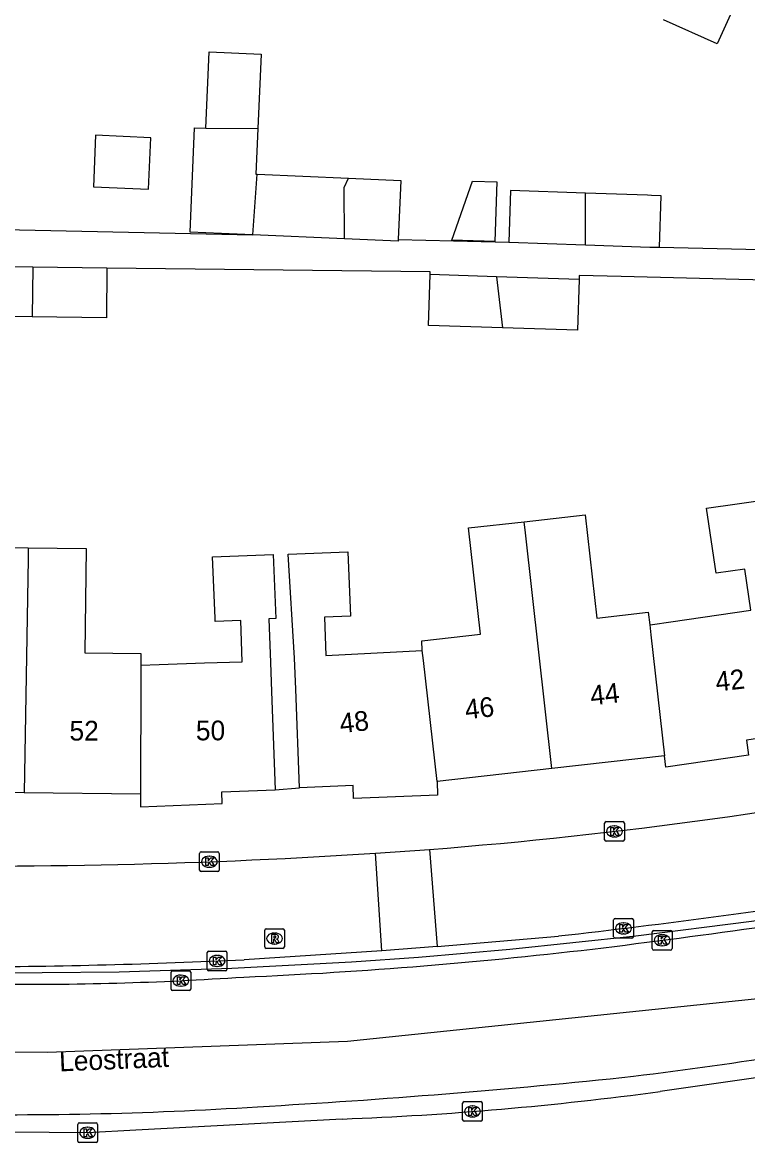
# Model space of a CAD drawing. Extents: x 161845 to 162341, y 381620 to 382158.
# Drawn here: x 162150.7 to 162187.5, y 381620.1 to 381677 of the extents above; entities that cross this region are included whole.
import ezdxf

# ---------------------------------------------------------------- set-up
doc = ezdxf.new("R2010")
doc.units = 0
for name, color, linetype in [('IMGEO_Hek', 7, 'Continuous'), ('IMGEO_Kolk', 7, 'Continuous'), ('IMGEO_Openbare_ruimte_label', 7, 'Continuous'), ('IMGEO_Pand', 7, 'Continuous'), ('IMGEO_Pand_nummerreeks', 7, 'Continuous'), ('IMGEO_Rijbaan_lokaal_open', 7, 'Continuous'), ('IMGEO_Rijbaan_regionaal_gesloten', 7, 'Continuous'), ('IMGEO_Rioolput', 7, 'Continuous'), ('IMGEO_Voetpad_open', 7, 'Continuous')]:
    doc.layers.add(name, color=color, linetype=linetype)

msp = doc.modelspace()

# ---------------------------------------------------------------- linework, layer by layer
at = {"layer": 'IMGEO_Hek'}
msp.add_lwpolyline([(162266.331, 381651.929), (162261.152, 381649.927), (162250.04, 381646.074), (162241.823, 381643.497), (162233.545, 381641.12), (162229.612, 381640.011), (162225.666, 381638.966), (162220.873, 381637.787), (162217.165, 381636.942), (162213.136, 381635.998), (162208.014, 381634.881), (162199.733, 381633.272), (162194.605, 381632.38), (162187.696, 381631.333), (162181.837, 381630.583), (162175.425, 381629.906), (162170.79, 381629.51), (162167.399, 381629.27), (162161.318, 381628.942), (162155.604, 381628.756), (162151.691, 381628.719), (162146.625, 381628.693)], dxfattribs=at)
at = {"layer": 'IMGEO_Kolk'}
for p, q in [((162180.245, 381635.482), (162180.245, 381636.334)), ((162180.32, 381636.408), (162181.172, 381636.408)), ((162180.733, 381636.188), (162180.758, 381636.188)), ((162181.246, 381636.334), (162181.246, 381635.482)), ((162180.756, 381635.628), (162180.731, 381635.628)), ((162181.172, 381635.408), (162180.32, 381635.408)), ((162159.68, 381633.943), (162159.68, 381634.795)), ((162159.755, 381634.869), (162160.607, 381634.869)), ((162160.168, 381634.649), (162160.193, 381634.649)), ((162160.681, 381634.795), (162160.681, 381633.943)), ((162160.607, 381633.869), (162159.755, 381633.869)), ((162160.191, 381634.089), (162160.166, 381634.089)), ((162180.779, 381631.485), (162181.631, 381631.485)), ((162180.704, 381630.559), (162180.704, 381631.411)), ((162181.192, 381631.265), (162181.217, 381631.265)), ((162181.705, 381631.411), (162181.705, 381630.559)), ((162181.631, 381630.485), (162180.779, 381630.485)), ((162181.215, 381630.705), (162181.19, 381630.705)), ((162182.666, 381629.955), (162182.666, 381630.807)), ((162182.741, 381630.881), (162183.593, 381630.881)), ((162183.154, 381630.661), (162183.179, 381630.661)), ((162183.667, 381630.807), (162183.667, 381629.955)), ((162160.144, 381629.83), (162160.996, 381629.83)), ((162183.593, 381629.881), (162182.741, 381629.881)), ((162183.177, 381630.101), (162183.152, 381630.101)), ((162160.069, 381628.904), (162160.069, 381629.756)), ((162160.557, 381629.61), (162160.582, 381629.61)), ((162161.07, 381629.756), (162161.07, 381628.904)), ((162158.231, 381627.904), (162158.231, 381628.756)), ((162158.306, 381628.83), (162159.158, 381628.83)), ((162159.232, 381628.756), (162159.232, 381627.904)), ((162160.996, 381628.83), (162160.144, 381628.83)), ((162160.58, 381629.05), (162160.555, 381629.05)), ((162158.719, 381628.61), (162158.744, 381628.61)), ((162159.158, 381627.83), (162158.306, 381627.83)), ((162158.742, 381628.05), (162158.717, 381628.05)), ((162173.035, 381621.26), (162173.035, 381622.112)), ((162173.11, 381622.186), (162173.962, 381622.186)), ((162173.523, 381621.966), (162173.548, 381621.966)), ((162174.036, 381622.112), (162174.036, 381621.26)), ((162173.546, 381621.406), (162173.521, 381621.406)), ((162153.497, 381620.18), (162153.497, 381621.032)), ((162153.572, 381621.106), (162154.424, 381621.106)), ((162153.985, 381620.886), (162154.01, 381620.886)), ((162154.498, 381621.032), (162154.498, 381620.18)), ((162173.962, 381621.186), (162173.11, 381621.186)), ((162154.424, 381620.106), (162153.572, 381620.106)), ((162154.008, 381620.326), (162153.983, 381620.326))]:
    msp.add_line(p, q, dxfattribs=at)
for points in [[(162180.245, 381635.482), (162180.245, 381636.334)], [(162180.32, 381636.408), (162181.172, 381636.408)], [(162180.566, 381636.108), (162180.689, 381636.108), (162180.689, 381635.957), (162180.819, 381636.108), (162180.983, 381636.108), (162180.837, 381635.957), (162180.99, 381635.708), (162180.838, 381635.708), (162180.753, 381635.872), (162180.689, 381635.805), (162180.689, 381635.708), (162180.566, 381635.708), (162180.566, 381636.108)], [(162181.246, 381636.334), (162181.246, 381635.482)], [(162181.172, 381635.408), (162180.32, 381635.408)], [(162159.68, 381633.943), (162159.68, 381634.795)], [(162159.755, 381634.869), (162160.607, 381634.869)], [(162160.001, 381634.569), (162160.124, 381634.569), (162160.124, 381634.418), (162160.254, 381634.569), (162160.418, 381634.569), (162160.272, 381634.418), (162160.425, 381634.169), (162160.273, 381634.169), (162160.188, 381634.333), (162160.124, 381634.266), (162160.124, 381634.169), (162160.001, 381634.169), (162160.001, 381634.569)], [(162160.681, 381634.795), (162160.681, 381633.943)], [(162160.607, 381633.869), (162159.755, 381633.869)], [(162180.779, 381631.485), (162181.631, 381631.485)], [(162180.704, 381630.559), (162180.704, 381631.411)], [(162181.025, 381631.185), (162181.148, 381631.185), (162181.148, 381631.034), (162181.278, 381631.185), (162181.442, 381631.185), (162181.296, 381631.034), (162181.449, 381630.785), (162181.297, 381630.785), (162181.212, 381630.949), (162181.148, 381630.882), (162181.148, 381630.785), (162181.025, 381630.785), (162181.025, 381631.185)], [(162181.705, 381631.411), (162181.705, 381630.559)], [(162181.631, 381630.485), (162180.779, 381630.485)], [(162182.666, 381629.955), (162182.666, 381630.807)], [(162182.741, 381630.881), (162183.593, 381630.881)], [(162182.987, 381630.581), (162183.11, 381630.581), (162183.11, 381630.43), (162183.24, 381630.581), (162183.404, 381630.581), (162183.258, 381630.43), (162183.411, 381630.181), (162183.259, 381630.181), (162183.174, 381630.345), (162183.11, 381630.278), (162183.11, 381630.181), (162182.987, 381630.181), (162182.987, 381630.581)], [(162183.667, 381630.807), (162183.667, 381629.955)], [(162160.144, 381629.83), (162160.996, 381629.83)], [(162183.593, 381629.881), (162182.741, 381629.881)], [(162160.069, 381628.904), (162160.069, 381629.756)], [(162160.39, 381629.53), (162160.513, 381629.53), (162160.513, 381629.379), (162160.643, 381629.53), (162160.807, 381629.53), (162160.661, 381629.379), (162160.814, 381629.13), (162160.662, 381629.13), (162160.577, 381629.294), (162160.513, 381629.227), (162160.513, 381629.13), (162160.39, 381629.13), (162160.39, 381629.53)], [(162161.07, 381629.756), (162161.07, 381628.904)], [(162158.231, 381627.904), (162158.231, 381628.756)], [(162158.306, 381628.83), (162159.158, 381628.83)], [(162159.232, 381628.756), (162159.232, 381627.904)], [(162160.996, 381628.83), (162160.144, 381628.83)], [(162158.552, 381628.53), (162158.675, 381628.53), (162158.675, 381628.379), (162158.805, 381628.53), (162158.969, 381628.53), (162158.823, 381628.379), (162158.976, 381628.13), (162158.824, 381628.13), (162158.739, 381628.294), (162158.675, 381628.227), (162158.675, 381628.13), (162158.552, 381628.13), (162158.552, 381628.53)], [(162159.158, 381627.83), (162158.306, 381627.83)], [(162173.035, 381621.26), (162173.035, 381622.112)], [(162173.11, 381622.186), (162173.962, 381622.186)], [(162173.356, 381621.886), (162173.479, 381621.886), (162173.479, 381621.735), (162173.609, 381621.886), (162173.773, 381621.886), (162173.627, 381621.735), (162173.78, 381621.486), (162173.628, 381621.486), (162173.543, 381621.65), (162173.479, 381621.583), (162173.479, 381621.486), (162173.356, 381621.486), (162173.356, 381621.886)], [(162174.036, 381622.112), (162174.036, 381621.26)], [(162153.497, 381620.18), (162153.497, 381621.032)], [(162153.572, 381621.106), (162154.424, 381621.106)], [(162153.818, 381620.806), (162153.941, 381620.806), (162153.941, 381620.655), (162154.071, 381620.806), (162154.235, 381620.806), (162154.089, 381620.655), (162154.242, 381620.406), (162154.09, 381620.406), (162154.005, 381620.57), (162153.941, 381620.503), (162153.941, 381620.406), (162153.818, 381620.406), (162153.818, 381620.806)], [(162154.498, 381621.032), (162154.498, 381620.18)], [(162173.962, 381621.186), (162173.11, 381621.186)], [(162154.424, 381620.106), (162153.572, 381620.106)]]:
    msp.add_lwpolyline(points, dxfattribs=at)
for centre, start, end in [((162180.322, 381636.332), 91.552, 178.448), ((162180.322, 381636.332), 91.552, 178.448), ((162181.17, 381636.332), 1.552, 88.448), ((162181.17, 381636.332), 1.552, 88.448), ((162180.322, 381635.484), 181.552, 268.448), ((162180.322, 381635.484), 181.552, 268.448), ((162181.17, 381635.484), 271.552, 358.448), ((162181.17, 381635.484), 271.552, 358.448), ((162159.757, 381634.793), 91.552, 178.448), ((162159.757, 381634.793), 91.552, 178.448), ((162160.605, 381634.793), 1.552, 88.448), ((162160.605, 381634.793), 1.552, 88.448), ((162159.757, 381633.945), 181.552, 268.448), ((162159.757, 381633.945), 181.552, 268.448), ((162160.605, 381633.945), 271.552, 358.448), ((162160.605, 381633.945), 271.552, 358.448), ((162180.781, 381631.409), 91.552, 178.448), ((162180.781, 381631.409), 91.552, 178.448), ((162181.629, 381631.409), 1.552, 88.448), ((162181.629, 381631.409), 1.552, 88.448), ((162180.781, 381630.561), 181.552, 268.448), ((162180.781, 381630.561), 181.552, 268.448), ((162181.629, 381630.561), 271.552, 358.448), ((162181.629, 381630.561), 271.552, 358.448), ((162182.743, 381630.805), 91.552, 178.448), ((162182.743, 381630.805), 91.552, 178.448), ((162183.591, 381630.805), 1.552, 88.448), ((162183.591, 381630.805), 1.552, 88.448), ((162160.146, 381629.754), 91.552, 178.448), ((162160.146, 381629.754), 91.552, 178.448), ((162160.994, 381629.754), 1.552, 88.448), ((162160.994, 381629.754), 1.552, 88.448), ((162182.743, 381629.957), 181.552, 268.448), ((162182.743, 381629.957), 181.552, 268.448), ((162183.591, 381629.957), 271.552, 358.448), ((162183.591, 381629.957), 271.552, 358.448), ((162158.308, 381628.754), 91.552, 178.448), ((162158.308, 381628.754), 91.552, 178.448), ((162159.156, 381628.754), 1.552, 88.448), ((162159.156, 381628.754), 1.552, 88.448), ((162160.146, 381628.906), 181.552, 268.448), ((162160.146, 381628.906), 181.552, 268.448), ((162160.994, 381628.906), 271.552, 358.448), ((162160.994, 381628.906), 271.552, 358.448), ((162158.308, 381627.906), 181.552, 268.448), ((162158.308, 381627.906), 181.552, 268.448), ((162159.156, 381627.906), 271.552, 358.448), ((162159.156, 381627.906), 271.552, 358.448), ((162173.112, 381622.11), 91.552, 178.448), ((162173.112, 381622.11), 91.552, 178.448), ((162173.96, 381622.11), 1.552, 88.448), ((162173.96, 381622.11), 1.552, 88.448), ((162173.112, 381621.262), 181.552, 268.448), ((162173.112, 381621.262), 181.552, 268.448), ((162173.96, 381621.262), 271.552, 358.448), ((162173.96, 381621.262), 271.552, 358.448), ((162153.574, 381621.03), 91.552, 178.448), ((162153.574, 381621.03), 91.552, 178.448), ((162154.422, 381621.03), 1.552, 88.448), ((162154.422, 381621.03), 1.552, 88.448), ((162153.574, 381620.182), 181.552, 268.448), ((162153.574, 381620.182), 181.552, 268.448), ((162154.422, 381620.182), 271.552, 358.448), ((162154.422, 381620.182), 271.552, 358.448)]:
    msp.add_arc(centre, 0.0765, start, end, dxfattribs=at)
for centre, major_axis, ratio, start_param, end_param in [((162180.732, 381635.908), (-0.387, 0.002), 0.722429, 4.712389, 7.853982), ((162180.757, 381635.908), (-0.39, 0.002), 0.717154, 1.570796, 4.712389), ((162160.167, 381634.369), (-0.387, 0.002), 0.722429, 4.712389, 7.853982), ((162160.192, 381634.369), (-0.39, 0.002), 0.717154, 1.570796, 4.712389), ((162181.191, 381630.985), (-0.387, 0.002), 0.722429, 4.712389, 7.853982), ((162181.216, 381630.985), (-0.39, 0.002), 0.717154, 1.570796, 4.712389), ((162183.153, 381630.381), (-0.387, 0.002), 0.722429, 4.712389, 7.853982), ((162183.178, 381630.381), (-0.39, 0.002), 0.717154, 1.570796, 4.712389), ((162160.556, 381629.33), (-0.387, 0.002), 0.722429, 4.712389, 7.853982), ((162160.581, 381629.33), (-0.39, 0.002), 0.717154, 1.570796, 4.712389), ((162158.718, 381628.33), (-0.387, 0.002), 0.722429, 4.712389, 7.853982), ((162158.743, 381628.33), (-0.39, 0.002), 0.717154, 1.570796, 4.712389), ((162173.522, 381621.686), (-0.387, 0.002), 0.722429, 4.712389, 7.853982), ((162173.547, 381621.686), (-0.39, 0.002), 0.717154, 1.570796, 4.712389), ((162153.984, 381620.606), (-0.387, 0.002), 0.722429, 4.712389, 7.853982), ((162154.009, 381620.606), (-0.39, 0.002), 0.717154, 1.570796, 4.712389)]:
    msp.add_ellipse(centre, major_axis=major_axis, ratio=ratio, start_param=start_param, end_param=end_param, dxfattribs=at)
at = {"layer": 'IMGEO_Pand'}
for points in [[(162190.591, 381679.708), (162188.176, 381680.797), (162185.966, 381675.897), (162183.238, 381677.127)], [(162160.004, 381671.628), (162160.17, 381675.495), (162162.804, 381675.382), (162162.643, 381671.603)], [(162162.379, 381666.199), (162159.203, 381666.335), (162159.429, 381671.633), (162160.004, 381671.628)], [(162160.004, 381671.628), (162162.643, 381671.603)], [(162162.643, 381671.603), (162162.544, 381669.286), (162162.599, 381669.283)], [(162154.399, 381671.259), (162154.288, 381668.649), (162157.089, 381668.529), (162157.2, 381671.139), (162154.399, 381671.259)], [(162162.379, 381666.199), (162162.599, 381669.283)], [(162162.599, 381669.283), (162167.235, 381669.085)], [(162167.032, 381666.001), (162167.021, 381668.61), (162167.235, 381669.085)], [(162167.235, 381669.085), (162169.897, 381668.972), (162169.769, 381665.971)], [(162174.778, 381668.888), (162174.667, 381665.86), (162172.483, 381665.935), (162173.545, 381668.931), (162174.778, 381668.888)], [(162179.271, 381668.325), (162175.473, 381668.458), (162175.381, 381665.835)], [(162179.274, 381665.7), (162179.271, 381668.325)], [(162183.031, 381665.574), (162183.122, 381668.19), (162182.625, 381668.207), (162182.42, 381668.215), (162179.271, 381668.325)], [(162167.032, 381666.001), (162162.379, 381666.199)], [(162169.769, 381665.971), (162169.765, 381665.884), (162167.032, 381666.001)], [(162175.381, 381665.835), (162179.274, 381665.7)], [(162179.274, 381665.7), (162182.534, 381665.586), (162183.031, 381665.574)], [(162151.173, 381662.038), (162145.389, 381662.105), (162145.39, 381662.215), (162145.413, 381664.229), (162145.417, 381664.537), (162145.418, 381664.622)], [(162151.214, 381664.561), (162145.418, 381664.622)], [(162151.214, 381664.561), (162151.173, 381662.038)], [(162154.979, 381664.517), (162154.977, 381664.363), (162154.975, 381664.185), (162154.973, 381664.02), (162154.956, 381662.482), (162154.95, 381661.994), (162151.173, 381662.038)], [(162154.979, 381664.517), (162151.214, 381664.561)], [(162175.054, 381661.485), (162171.3, 381661.606), (162171.383, 381664.183)], [(162174.763, 381664.074), (162171.383, 381664.183)], [(162178.947, 381663.939), (162174.763, 381664.074)], [(162174.763, 381664.074), (162175.054, 381661.485)], [(162178.947, 381663.939), (162178.864, 381661.362), (162175.054, 381661.485)], [(162182.533, 381646.399), (162182.672, 381646.419), (162183.599, 381646.553), (162187.664, 381647.139), (162187.362, 381649.229), (162185.9, 381649.018), (162185.423, 381652.319), (162188.649, 381652.784), (162189.282, 381647.391), (162189.493, 381645.896), (162190.207, 381640.947)], [(162176.159, 381651.636), (162179.257, 381651.984), (162179.846, 381646.744), (162182.462, 381647.039), (162182.533, 381646.399)], [(162170.99, 381645.089), (162170.97, 381645.585), (162173.949, 381645.919), (162173.342, 381651.319), (162176.159, 381651.636)], [(162177.565, 381639.1), (162176.222, 381651.071), (162176.159, 381651.636)], [(162145.029, 381644.333), (162145.037, 381645.017), (162147.895, 381644.984), (162147.956, 381650.344), (162150.981, 381650.309)], [(162150.981, 381650.309), (162150.972, 381649.753), (162150.778, 381637.873)], [(162150.981, 381650.309), (162153.916, 381650.276), (162153.856, 381644.979), (162156.693, 381644.947), (162156.691, 381644.345)], [(162156.691, 381644.345), (162157.627, 381644.382), (162159.933, 381644.471), (162161.845, 381644.522), (162161.777, 381646.62), (162160.47, 381646.572), (162160.467, 381646.734), (162160.345, 381649.858), (162163.425, 381649.978), (162163.553, 381646.718), (162163.198, 381646.705), (162163.281, 381644.485), (162163.332, 381643.016), (162163.527, 381638.019)], [(162164.759, 381638.129), (162164.564, 381643.126), (162164.508, 381644.705), (162164.185, 381649.986), (162167.213, 381650.104), (162167.34, 381646.839), (162166.016, 381646.788), (162166.092, 381644.841), (162170.99, 381645.089)], [(162182.533, 381646.399), (162182.59, 381645.891), (162183.28, 381639.742)], [(162171.735, 381638.445), (162171.046, 381644.594), (162170.99, 381645.089)], [(162156.691, 381644.345), (162156.69, 381643.846), (162156.685, 381637.805)], [(162190.207, 381640.947), (162187.44, 381640.547), (162187.55, 381639.782), (162183.361, 381639.177), (162183.28, 381639.742)], [(162183.28, 381639.742), (162177.565, 381639.1)], [(162177.565, 381639.1), (162171.735, 381638.445)], [(162171.735, 381638.445), (162171.763, 381637.741), (162167.497, 381637.575), (162167.471, 381638.234), (162164.759, 381638.129)], [(162150.778, 381637.873), (162144.955, 381637.94)], [(162156.685, 381637.805), (162150.778, 381637.873)], [(162156.685, 381637.805), (162156.685, 381637.16), (162160.835, 381637.322), (162160.812, 381637.913), (162163.527, 381638.019)]]:
    msp.add_lwpolyline(points, dxfattribs=at)
at = {"layer": 'IMGEO_Rijbaan_lokaal_open'}
for points in [[(162168.608, 381634.796), (162171.352, 381634.993)], [(162171.352, 381634.993), (162171.735, 381630.057)], [(162164.882, 381634.579), (162168.608, 381634.796)], [(162168.935, 381629.843), (162168.608, 381634.796)], [(162171.735, 381630.057), (162177.896, 381630.597)], [(162168.935, 381629.843), (162161.938, 381629.394)], [(162171.735, 381630.057), (162168.935, 381629.843)]]:
    msp.add_lwpolyline(points, dxfattribs=at)
for centre, radius, start, end in [((162152.698, 381874.845), 240.576, 274.44717, 281.32872), ((162148.33, 381951.653), 317.505, 268.07742, 272.98826), ((162125.277, 382092.031), 464.424, 276.5055, 278.52512), ((162146.248, 381962.51), 333.485, 270.29048, 272.69663)]:
    msp.add_arc(centre, radius, start, end, dxfattribs=at)
at = {"layer": 'IMGEO_Rijbaan_regionaal_gesloten'}
for points in [[(162065.762, 381627.224), (162074.598, 381626.568), (162101.225, 381625.613), (162133.688, 381624.885), (162151.965, 381624.703), (162167.196, 381625.249), (162193.384, 381627.978), (162217.254, 381632.709), (162234.44, 381637.075), (162251.353, 381642.169), (162267.176, 381648.082), (162286.544, 381657.725), (162299.911, 381665.73), (162311.76, 381673.667)], [(162213.216, 381627.95), (162202.615, 381625.821), (162196.222, 381624.571), (162183.072, 381622.703)], [(162166.914, 381621.301), (162156.441, 381620.733), (162153.994, 381620.605), (162134.53, 381620.776), (162126.197, 381620.966), (162114.837, 381621.198), (162100.02, 381621.534), (162090.138, 381621.864), (162075.85, 381622.469), (162074.337, 381622.567), (162068.187, 381622.967), (162063.349, 381623.412)]]:
    msp.add_lwpolyline(points, dxfattribs=at)
for centre, radius, start, end in [((162127.7, 382058.233), 431.434, 276.98858, 279.33403), ((162151.953, 381863.5), 235.198, 272.43023, 276.89611), ((162151.029, 381789.499), 161.353, 269.28923, 273.87258), ((162124.819, 382065.373), 445.546, 277.3365, 279.40852), ((162140.329, 382015.292), 393.997, 273.24446, 276.02937), ((162160.554, 381788.41), 167.23, 272.17954, 277.73852), ((162150.09, 381816.832), 195.309, 268.69218, 273.68076)]:
    msp.add_arc(centre, radius, start, end, dxfattribs=at)
at = {"layer": 'IMGEO_Rioolput'}
for p, q in [((162163.062, 381630.969), (162163.914, 381630.969)), ((162162.987, 381630.043), (162162.987, 381630.895)), ((162163.475, 381630.749), (162163.5, 381630.749)), ((162163.988, 381630.895), (162163.988, 381630.043)), ((162163.914, 381629.969), (162163.062, 381629.969)), ((162163.498, 381630.189), (162163.473, 381630.189))]:
    msp.add_line(p, q, dxfattribs=at)
for points in [[(162163.062, 381630.969), (162163.914, 381630.969)], [(162162.987, 381630.043), (162162.987, 381630.895)], [(162163.576, 381630.667), (162163.324, 381630.669), (162163.324, 381630.269)], [(162163.324, 381630.269), (162163.448, 381630.269), (162163.448, 381630.431), (162163.459, 381630.431)], [(162163.502, 381630.588), (162163.448, 381630.588), (162163.448, 381630.507)], [(162163.448, 381630.507), (162163.5, 381630.507)], [(162163.506, 381630.402), (162163.577, 381630.269), (162163.717, 381630.269), (162163.652, 381630.395)], [(162163.988, 381630.895), (162163.988, 381630.043)], [(162163.914, 381629.969), (162163.062, 381629.969)]]:
    msp.add_lwpolyline(points, dxfattribs=at)
for centre, radius, start, end in [((162163.064, 381630.893), 0.0765, 91.552, 178.448), ((162163.064, 381630.893), 0.0765, 91.552, 178.448), ((162163.912, 381630.893), 0.0765, 1.552, 88.448), ((162163.912, 381630.893), 0.0765, 1.552, 88.448), ((162163.458, 381630.378), 0.0533, 26.0293, 88.6989), ((162163.484, 381630.696), 0.19, 274.7715, 282.9687), ((162163.508, 381630.492), 0.0964, 77.0061, 93.1865), ((162163.522, 381630.549), 0.0378, 276.6634, 79.6772), ((162163.575, 381630.557), 0.109, 350.3612, 89.416), ((162163.573, 381630.557), 0.112, 277.5842, 350.9817), ((162163.557, 381630.342), 0.108, 29.5134, 73.7905), ((162163.064, 381630.045), 0.0765, 181.552, 268.448), ((162163.064, 381630.045), 0.0765, 181.552, 268.448), ((162163.912, 381630.045), 0.0765, 271.552, 358.448), ((162163.912, 381630.045), 0.0765, 271.552, 358.448)]:
    msp.add_arc(centre, radius, start, end, dxfattribs=at)
for centre, major_axis, ratio, start_param, end_param in [((162163.474, 381630.469), (-0.387, 0.002), 0.722429, 4.712389, 7.853982), ((162163.499, 381630.469), (-0.39, 0.002), 0.717154, 1.570796, 4.712389)]:
    msp.add_ellipse(centre, major_axis=major_axis, ratio=ratio, start_param=start_param, end_param=end_param, dxfattribs=at)
at = {"layer": 'IMGEO_Voetpad_open'}
for points in [[(162145.006, 381666.572), (162162.379, 381666.199)], [(162169.769, 381665.971), (162175.381, 381665.835)], [(162183.031, 381665.574), (162201.323, 381665.149)], [(162171.383, 381664.183), (162171.387, 381664.319), (162154.979, 381664.517)], [(162197.044, 381663.693), (162187.051, 381663.936), (162181.089, 381664.081), (162178.953, 381664.133), (162178.947, 381663.939)], [(162163.527, 381638.019), (162164.759, 381638.129)]]:
    msp.add_lwpolyline(points, dxfattribs=at)

# ---------------------------------------------------------------- texts
at = {"layer": 'IMGEO_Openbare_ruimte_label'}
msp.add_text('Leostraat', height=1, rotation=2.4074, dxfattribs=at).set_placement((162152.572, 381623.718))
at = {"layer": 'IMGEO_Pand_nummerreeks'}
for s, rotation, p in [('42', 6.3197, (162185.925, 381643.008)), ('44', 6.3197, (162179.566, 381642.304)), ('46', 6.3189, (162173.203, 381641.599)), ('48', 6.3189, (162166.844, 381640.895)), ('52', 0.0917, (162153.077, 381640.522)), ('50', 0.0917, (162159.494, 381640.533))]:
    msp.add_text(s, height=1, rotation=rotation, dxfattribs=at).set_placement(p)

doc.saveas('drawing.dxf')
